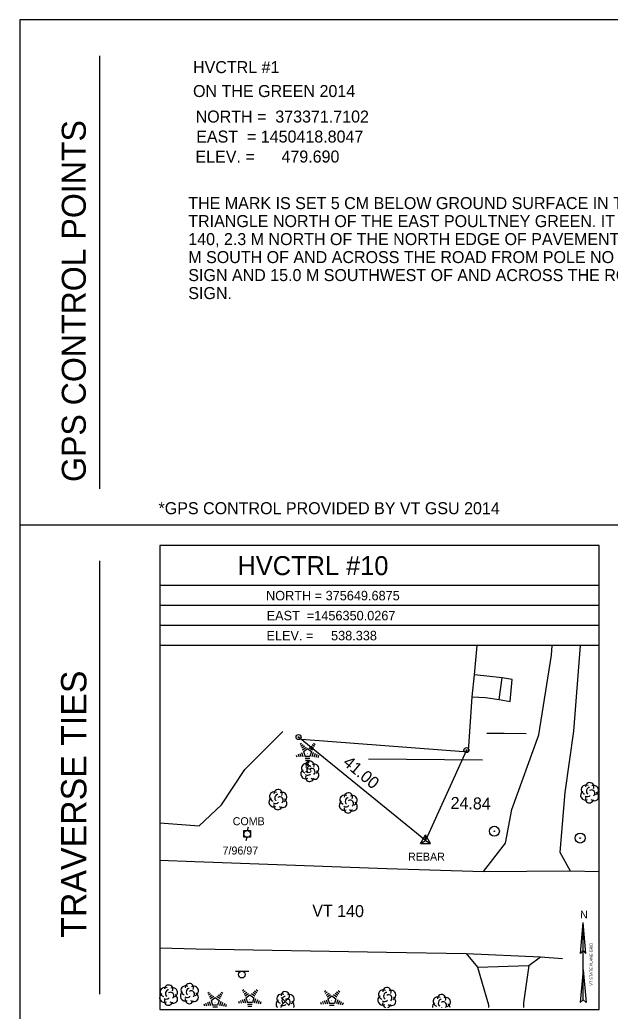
# Model space of a CAD drawing. Extents: x 1454446 to 1455086, y 375501 to 375921.
# Drawn here: x 1454446.4 to 1454594.1, y 375672.7 to 375920.6 of the extents above; entities that cross this region are included whole.
import ezdxf

# ---------------------------------------------------------------- set-up
doc = ezdxf.new("R2010")
doc.units = 0
for name, color, linetype in [('C_A', 7, 'Continuous'), ('CBP', 7, 'Continuous'), ('CPSM', 7, 'Continuous'), ('Default', 7, 'Continuous'), ('L_A', 7, 'Continuous'), ('L_TIC', 7, 'Continuous'), ('LAHR', 7, 'Continuous'), ('LAWA', 7, 'Continuous'), ('LBC', 7, 'Continuous'), ('LDEFAULT', 7, 'Continuous'), ('LTC', 7, 'Continuous'), ('LTD', 7, 'Continuous'), ('NBL1', 7, 'Continuous'), ('NBL2', 7, 'Continuous'), ('NNA_P', 7, 'Continuous'), ('PET', 7, 'Continuous'), ('RDG', 7, 'Continuous'), ('RDP', 7, 'Continuous'), ('RGP', 7, 'Continuous'), ('RSW', 7, 'Continuous'), ('SSGN', 7, 'Continuous'), ('U_A', 7, 'Continuous'), ('U_C', 7, 'Continuous'), ('UP', 7, 'Continuous')]:
    doc.layers.add(name, color=color, linetype=linetype)

msp = doc.modelspace()

# ---------------------------------------------------------------- linework, layer by layer
at = {"layer": 'CBP'}
for centre, radius in [((1454516.11, 375741.22), 0.625), ((1454516.11, 375741.22), 0.0833), ((1454558.12, 375737.95), 0.625), ((1454558.12, 375737.95), 0.0833)]:
    msp.add_circle(centre, radius, dxfattribs=at)
at = {"layer": 'CPSM'}
for p, q in [((1454546.66, 375714.58), (1454547.91, 375716.75)), ((1454549.16, 375714.58), (1454547.91, 375716.75)), ((1454547.91, 375715.31), (1454547.91, 375716.75)), ((1454546.66, 375714.58), (1454547.91, 375715.31)), ((1454546.66, 375714.58), (1454549.16, 375714.58)), ((1454547.91, 375715.31), (1454547.91, 375715.31)), ((1454547.91, 375715.31), (1454549.16, 375714.58))]:
    msp.add_line(p, q, dxfattribs=at)
at = {"layer": 'Default'}
for p, q in [((1454547.91, 375715.31), (1454516.11, 375741.22)), ((1454558.12, 375737.95), (1454547.91, 375715.31))]:
    msp.add_line(p, q, dxfattribs=at)
at = {"layer": 'L_TIC'}
for points in [[(1454511.74, 375674.07), (1454513.74, 375676.07)], [(1454513.74, 375674.07), (1454511.74, 375676.07)]]:
    msp.add_lwpolyline(points, dxfattribs=at)
at = {"layer": 'LAHR'}
for points in [[(1454563.24, 375742.16), (1454567.54, 375742.19), (1454573.08, 375742.15)], [(1454533.64, 375735.77), (1454562.16, 375735.5)]]:
    msp.add_lwpolyline(points, dxfattribs=at)
at = {"layer": 'LAWA'}
msp.add_lwpolyline([(1454481.37, 375719.77), (1454491.29, 375719), (1454496.85, 375724.26), (1454502.72, 375733.1), (1454512.21, 375742.64)], dxfattribs=at)
at = {"layer": 'LBC'}
msp.add_lwpolyline([(1454515.8, 375740.76), (1454558.56, 375737.56), (1454558.69, 375738.88), (1454559.56, 375751.32), (1454560.16, 375756.81), (1454560.84, 375764.1)], dxfattribs=at)
at = {"layer": 'LDEFAULT'}
msp.add_lwpolyline([(1454559.56, 375751.32), (1454562.87, 375751.13), (1454566.34, 375750.63), (1454567.11, 375756.03), (1454560.16, 375756.81)], dxfattribs=at)
at = {"layer": 'LTC'}
for p, q in [((1454516.5, 375739.44), (1454516.86, 375739.7)), ((1454516.71, 375738.97), (1454517.24, 375739.36)), ((1454516.92, 375738.51), (1454517.62, 375739.02)), ((1454517.13, 375738.04), (1454518.01, 375738.68)), ((1454517.35, 375737.59), (1454518.37, 375738.32)), ((1454518.37, 375738.32), (1454519.36, 375737.6)), ((1454518.79, 375738.64), (1454519.6, 375738.05)), ((1454519.16, 375738.98), (1454519.84, 375738.49)), ((1454519.53, 375739.33), (1454520.08, 375738.93)), ((1454519.9, 375739.68), (1454520.32, 375739.38)), ((1454515.53, 375736.72), (1454515.69, 375736.25)), ((1454515.99, 375736.94), (1454516.2, 375736.28)), ((1454516.44, 375737.15), (1454516.72, 375736.32)), ((1454516.9, 375737.37), (1454517.23, 375736.35)), ((1454517.35, 375737.59), (1454517.74, 375736.39)), ((1454518.97, 375736.39), (1454517.74, 375736.39)), ((1454518.93, 375735.89), (1454517.79, 375735.89)), ((1454518.85, 375735.39), (1454517.86, 375735.39)), ((1454519.36, 375737.6), (1454518.97, 375736.39)), ((1454519.8, 375737.33), (1454519.46, 375736.29)), ((1454520.25, 375737.08), (1454519.96, 375736.19)), ((1454520.69, 375736.83), (1454520.45, 375736.1)), ((1454521.13, 375736.58), (1454520.95, 375736)), ((1454518.77, 375734.89), (1454517.93, 375734.89)), ((1454518.68, 375734.39), (1454518.01, 375734.39)), ((1454493.39, 375677.19), (1454493.74, 375677.45)), ((1454493.6, 375676.73), (1454494.12, 375677.11)), ((1454493.81, 375676.26), (1454494.51, 375676.77)), ((1454494.01, 375675.8), (1454494.89, 375676.43)), ((1454494.24, 375675.34), (1454495.25, 375676.08)), ((1454495.25, 375676.08), (1454496.25, 375675.35)), ((1454495.67, 375676.39), (1454496.48, 375675.8)), ((1454496.04, 375676.74), (1454496.72, 375676.24)), ((1454496.41, 375677.09), (1454496.96, 375676.69)), ((1454496.78, 375677.43), (1454497.2, 375677.13)), ((1454502.09, 375677.85), (1454502.45, 375678.11)), ((1454502.3, 375677.39), (1454502.83, 375677.77)), ((1454502.49, 375675.78), (1454502.82, 375674.76)), ((1454502.51, 375676.92), (1454503.21, 375677.43)), ((1454502.72, 375676.46), (1454503.6, 375677.1)), ((1454502.94, 375676), (1454503.96, 375676.74)), ((1454502.94, 375676), (1454503.33, 375674.81)), ((1454503.96, 375676.74), (1454504.95, 375676.01)), ((1454504.38, 375677.05), (1454505.19, 375676.46)), ((1454504.95, 375676.01), (1454504.56, 375674.81)), ((1454504.75, 375677.4), (1454505.43, 375676.9)), ((1454505.39, 375675.74), (1454505.05, 375674.7)), ((1454505.12, 375677.75), (1454505.67, 375677.35)), ((1454505.49, 375678.09), (1454505.91, 375677.79)), ((1454522.62, 375677.61), (1454522.97, 375677.87)), ((1454522.82, 375677.14), (1454523.35, 375677.53)), ((1454523.03, 375676.68), (1454523.74, 375677.19)), ((1454523.24, 375676.21), (1454524.12, 375676.85)), ((1454523.47, 375675.76), (1454524.48, 375676.49)), ((1454523.47, 375675.76), (1454523.86, 375674.56)), ((1454524.48, 375676.49), (1454525.48, 375675.77)), ((1454524.9, 375676.8), (1454525.71, 375676.22)), ((1454525.48, 375675.77), (1454525.09, 375674.56)), ((1454525.27, 375677.15), (1454525.95, 375676.66)), ((1454525.64, 375677.5), (1454526.19, 375677.1)), ((1454526.01, 375677.85), (1454526.43, 375677.54)), ((1454492.42, 375674.47), (1454492.57, 375674)), ((1454492.87, 375674.69), (1454493.09, 375674.04)), ((1454493.33, 375674.91), (1454493.6, 375674.07)), ((1454493.78, 375675.12), (1454494.12, 375674.1)), ((1454494.24, 375675.34), (1454494.63, 375674.15)), ((1454495.86, 375674.15), (1454494.63, 375674.15)), ((1454495.82, 375673.65), (1454494.67, 375673.65)), ((1454496.25, 375675.35), (1454495.86, 375674.15)), ((1454496.69, 375675.08), (1454496.35, 375674.04)), ((1454497.13, 375674.83), (1454496.84, 375673.94)), ((1454497.57, 375674.58), (1454497.34, 375673.85)), ((1454498.02, 375674.33), (1454497.83, 375673.75)), ((1454501.12, 375675.13), (1454501.28, 375674.67)), ((1454501.58, 375675.35), (1454501.79, 375674.7)), ((1454502.03, 375675.57), (1454502.31, 375674.73)), ((1454504.56, 375674.81), (1454503.33, 375674.81)), ((1454504.52, 375674.31), (1454503.38, 375674.31)), ((1454504.44, 375673.81), (1454503.45, 375673.81)), ((1454505.83, 375675.49), (1454505.55, 375674.61)), ((1454506.28, 375675.24), (1454506.04, 375674.51)), ((1454506.72, 375674.99), (1454506.54, 375674.42)), ((1454521.65, 375674.89), (1454521.8, 375674.42)), ((1454522.1, 375675.1), (1454522.31, 375674.45)), ((1454522.56, 375675.32), (1454522.83, 375674.49)), ((1454523.01, 375675.54), (1454523.34, 375674.52)), ((1454525.09, 375674.56), (1454523.86, 375674.56)), ((1454525.05, 375674.06), (1454523.9, 375674.06)), ((1454525.91, 375675.5), (1454525.58, 375674.46)), ((1454526.36, 375675.24), (1454526.07, 375674.36)), ((1454526.8, 375674.99), (1454526.57, 375674.27)), ((1454527.25, 375674.74), (1454527.06, 375674.17))]:
    msp.add_line(p, q, dxfattribs=at)
at = {"layer": 'LTD'}
for p, q in [((1454518.92, 375732.69), (1454518.92, 375732.69)), ((1454518.92, 375732.69), (1454518.92, 375732.69)), ((1454510.94, 375725.63), (1454510.94, 375725.63)), ((1454510.94, 375725.63), (1454510.94, 375725.63)), ((1454588.93, 375727.34), (1454588.93, 375727.34)), ((1454588.93, 375727.34), (1454588.93, 375727.34)), ((1454528.55, 375724.81), (1454528.55, 375724.81)), ((1454528.55, 375724.81), (1454528.55, 375724.81)), ((1454483.58, 375676.73), (1454483.58, 375676.73)), ((1454483.58, 375676.73), (1454483.58, 375676.73)), ((1454488.78, 375677.12), (1454488.78, 375677.12)), ((1454488.78, 375677.12), (1454488.78, 375677.12)), ((1454538.18, 375676.11), (1454538.18, 375676.11)), ((1454538.18, 375676.11), (1454538.18, 375676.11)), ((1454512.74, 375675.07), (1454512.74, 375675.07)), ((1454512.74, 375675.07), (1454512.74, 375675.07))]:
    msp.add_line(p, q, dxfattribs=at)
for centre in [(1454518.97, 375734.13), (1454510.99, 375727.07), (1454588.98, 375728.77), (1454528.6, 375726.24), (1454483.63, 375678.16), (1454488.83, 375678.55), (1454538.23, 375677.54), (1454512.78, 375676.5), (1454551.9, 375675.77)]:
    msp.add_arc(centre, 1.05, 335.5272, 180.9563, dxfattribs=at)
for centre, major_axis, ratio, start_param, end_param in [((1454517.84, 375731.98), (0.58, -1.04), 0.959034, 3.141593, 6.283185), ((1454518.13, 375733.36), (1.21, -0.51), 0.895232, 1.570796, 4.712389), ((1454518.72, 375733.15), (-0.208, -0.792), 0.645439, 3.141593, 6.283185), ((1454519.42, 375732.53), (-0.5, 0.667), 0.989748, 3.141593, 6.283185), ((1454519.92, 375731.86), (-1.09, 0.79), 0.841452, 1.570796, 4.712389), ((1454519.97, 375733.28), (-1.14, -0.48), 0.949671, 1.570796, 4.712389), ((1454518.92, 375731.19), (0.26, 1.06), 0.942809, 1.570796, 4.712389), ((1454518.47, 375731.94), (-0.625, -0.083), 0.423636, 0, 3.141593), ((1454588.14, 375728.01), (1.21, -0.51), 0.895232, 1.570796, 4.712389), ((1454588.72, 375727.8), (-0.208, -0.792), 0.645439, 3.141593, 6.283185), ((1454589.43, 375727.17), (-0.5, 0.667), 0.989748, 3.141593, 6.283185), ((1454589.97, 375727.92), (-1.14, -0.48), 0.949671, 1.570796, 4.712389), ((1454509.86, 375724.92), (0.58, -1.04), 0.959034, 3.141593, 6.283185), ((1454510.15, 375726.3), (1.21, -0.51), 0.895232, 1.570796, 4.712389), ((1454510.73, 375726.09), (-0.208, -0.792), 0.645439, 3.141593, 6.283185), ((1454511.44, 375725.46), (-0.5, 0.667), 0.989748, 3.141593, 6.283185), ((1454511.94, 375724.8), (-1.09, 0.79), 0.841452, 1.570796, 4.712389), ((1454511.98, 375726.21), (-1.14, -0.48), 0.949671, 1.570796, 4.712389), ((1454527.76, 375725.48), (1.21, -0.51), 0.895232, 1.570796, 4.712389), ((1454528.34, 375725.27), (-0.208, -0.792), 0.645439, 3.141593, 6.283185), ((1454529.05, 375724.64), (-0.5, 0.667), 0.989748, 3.141593, 6.283185), ((1454529.59, 375725.39), (-1.14, -0.48), 0.949671, 1.570796, 4.712389), ((1454587.85, 375726.63), (0.58, -1.04), 0.959034, 3.141593, 6.283185), ((1454588.93, 375725.84), (0.26, 1.06), 0.942809, 1.570796, 4.712389), ((1454588.47, 375726.59), (-0.625, -0.083), 0.423636, 0, 3.141593), ((1454589.93, 375726.51), (-1.09, 0.79), 0.841452, 1.570796, 4.712389), ((1454510.94, 375724.13), (0.26, 1.06), 0.942809, 1.570796, 4.712389), ((1454510.48, 375724.88), (-0.625, -0.083), 0.423636, 0, 3.141593), ((1454527.47, 375724.1), (0.58, -1.04), 0.959034, 3.141593, 6.283185), ((1454528.55, 375723.31), (0.26, 1.06), 0.942809, 1.570796, 4.712389), ((1454528.09, 375724.06), (-0.625, -0.083), 0.423636, 0, 3.141593), ((1454529.55, 375723.98), (-1.09, 0.79), 0.841452, 1.570796, 4.712389), ((1454482.79, 375677.39), (1.21, -0.51), 0.895232, 1.570796, 4.712389), ((1454484.62, 375677.31), (-1.14, -0.48), 0.949671, 1.570796, 4.712389), ((1454487.99, 375677.79), (1.21, -0.51), 0.895232, 1.570796, 4.712389), ((1454488.58, 375677.58), (-0.208, -0.792), 0.645439, 3.141593, 6.283185), ((1454489.83, 375677.7), (-1.14, -0.48), 0.949671, 1.570796, 4.712389), ((1454482.5, 375676.02), (0.58, -1.04), 0.959034, 3.141593, 6.283185), ((1454483.12, 375675.98), (-0.625, -0.083), 0.423636, 0, 3.141593), ((1454483.37, 375677.19), (-0.208, -0.792), 0.645439, 3.141593, 6.283185), ((1454484.08, 375676.56), (-0.5, 0.667), 0.989748, 3.141593, 6.283185), ((1454484.58, 375675.89), (-1.09, 0.79), 0.841452, 1.570796, 4.712389), ((1454487.7, 375676.41), (0.58, -1.04), 0.959034, 3.141593, 6.283185), ((1454488.78, 375675.62), (0.26, 1.06), 0.942809, 1.570796, 4.712389), ((1454488.33, 375676.37), (-0.625, -0.083), 0.423636, 0, 3.141593), ((1454489.28, 375676.95), (-0.5, 0.667), 0.989748, 3.141593, 6.283185), ((1454489.78, 375676.29), (-1.09, 0.79), 0.841452, 1.570796, 4.712389), ((1454511.95, 375675.74), (1.21, -0.51), 0.895232, 1.570796, 4.712389), ((1454512.53, 375675.53), (-0.208, -0.792), 0.645439, 3.141593, 6.283185), ((1454513.24, 375674.9), (-0.5, 0.667), 0.989748, 3.141593, 6.283185), ((1454513.78, 375675.65), (-1.14, -0.48), 0.949671, 1.570796, 4.712389), ((1454537.1, 375675.4), (0.58, -1.04), 0.959034, 3.141593, 6.283185), ((1454537.39, 375676.78), (1.21, -0.51), 0.895232, 1.570796, 4.712389), ((1454537.97, 375676.57), (-0.208, -0.792), 0.645439, 3.141593, 6.283185), ((1454538.68, 375675.94), (-0.5, 0.667), 0.989748, 3.141593, 6.283185), ((1454539.18, 375675.28), (-1.09, 0.79), 0.841452, 1.570796, 4.712389), ((1454539.22, 375676.69), (-1.14, -0.48), 0.949671, 1.570796, 4.712389), ((1454551.06, 375675), (1.21, -0.51), 0.895232, 1.570796, 4.712389), ((1454552.89, 375674.92), (-1.14, -0.48), 0.949671, 1.570796, 4.712389), ((1454483.58, 375675.23), (0.26, 1.06), 0.942809, 1.570796, 4.712389), ((1454511.65, 375674.36), (0.58, -1.04), 0.959034, 3.141593, 4.952371), ((1454512.28, 375674.32), (-0.625, -0.083), 0.423636, 0, 3.141593), ((1454512.74, 375673.57), (0.26, 1.06), 0.942809, 1.570796, 1.801797), ((1454513.74, 375674.24), (-1.09, 0.79), 0.841452, 3.271651, 4.712389), ((1454538.18, 375674.61), (0.26, 1.06), 0.942809, 1.570796, 3.07315), ((1454537.72, 375675.36), (-0.625, -0.083), 0.423636, 0, 3.141593), ((1454538.18, 375674.61), (0.26, 1.06), 0.942809, 3.672659, 4.712389), ((1454550.77, 375673.63), (0.58, -1.04), 0.959034, 3.141593, 4.267083), ((1454551.64, 375674.79), (-0.208, -0.792), 0.645439, 3.141593, 6.283185), ((1454552.35, 375674.17), (-0.5, 0.667), 0.989748, 3.268895, 6.283185), ((1454551.39, 375673.58), (-0.625, -0.083), 0.423636, 2.782802, 3.141593), ((1454552.85, 375673.5), (-1.09, 0.79), 0.841452, 3.910504, 4.712389)]:
    msp.add_ellipse(centre, major_axis=major_axis, ratio=ratio, start_param=start_param, end_param=end_param, dxfattribs=at)
at = {"layer": 'NBL1'}
msp.add_lwpolyline([(1454446.38, 375500.6), (1455086.38, 375500.6), (1455086.38, 375920.6), (1454446.38, 375920.6)], close=True, dxfattribs=at)
at = {"layer": 'NBL2'}
for p, q in [((1454466.38, 375803.27), (1454466.38, 375911.6)), ((1454446.38, 375794.27), (1455086.38, 375794.27)), ((1454466.38, 375676.93), (1454466.38, 375785.27)), ((1454591.37, 375779.1), (1454481.37, 375779.1)), ((1454591.37, 375774.1), (1454481.37, 375774.1)), ((1454591.37, 375769.1), (1454481.37, 375769.1)), ((1454591.37, 375764.1), (1454481.37, 375764.1))]:
    msp.add_line(p, q, dxfattribs=at)
msp.add_lwpolyline([(1454481.37, 375673.1), (1454591.37, 375673.1), (1454591.37, 375789.1), (1454481.37, 375789.1)], close=True, dxfattribs=at)
at = {"layer": 'NNA_P'}
for p, q in [((1454586.64, 375687.06), (1454587.33, 375694.85)), ((1454587.33, 375675.47), (1454587.33, 375694.85)), ((1454588.02, 375687.06), (1454587.33, 375694.85)), ((1454586.64, 375687.06), (1454587.33, 375687.82)), ((1454588.03, 375687.06), (1454587.33, 375687.82)), ((1454587.34, 375683), (1454586.61, 375674.83)), ((1454587.33, 375683), (1454588.05, 375674.83)), ((1454587.33, 375675.47), (1454586.61, 375674.83)), ((1454587.33, 375675.47), (1454588.05, 375674.83))]:
    msp.add_line(p, q, dxfattribs=at)
at = {"layer": 'PET'}
for points in [[(1454481.37, 375710.41), (1454490.17, 375710.09), (1454538.2, 375708.32), (1454562.37, 375707.63), (1454584.1, 375707.8), (1454591.37, 375707.56)], [(1454481.37, 375688.53), (1454490.52, 375688.27), (1454538.1, 375687.4), (1454558.04, 375687.09), (1454576.68, 375686.22), (1454582.19, 375685.84)]]:
    msp.add_lwpolyline(points, dxfattribs=at)
at = {"layer": 'RDG'}
for points in [[(1454562.37, 375707.63), (1454567.94, 375714.69), (1454569.53, 375723.08), (1454576.27, 375741.78), (1454579.43, 375761.7), (1454579.6, 375764.1)], [(1454586.6, 375764.1), (1454584.88, 375742.71), (1454582.74, 375727.36), (1454581.52, 375712.44), (1454584.1, 375707.8)], [(1454560.93, 375683.63), (1454563.64, 375674.21), (1454563.68, 375673.57)], [(1454573.73, 375684.05), (1454572.44, 375674.75), (1454572.43, 375673.57)]]:
    msp.add_lwpolyline(points, dxfattribs=at)
at = {"layer": 'RDP'}
msp.add_lwpolyline([(1454558.04, 375687.09), (1454560.93, 375683.63), (1454573.73, 375684.05), (1454576.68, 375686.22)], dxfattribs=at)
at = {"layer": 'RGP'}
for p, q in [((1454565.12, 375717.66), (1454565.12, 375717.66)), ((1454586.59, 375715.97), (1454586.59, 375715.97))]:
    msp.add_line(p, q, dxfattribs=at)
for centre, radius in [((1454565.12, 375717.66), 1.25), ((1454565.12, 375717.66), 0.0833), ((1454586.59, 375715.97), 1.25), ((1454586.59, 375715.97), 0.0833)]:
    msp.add_circle(centre, radius, dxfattribs=at)
at = {"layer": 'RSW'}
msp.add_lwpolyline([(1454566.34, 375750.63), (1454569.05, 375750.14), (1454569.54, 375755.62), (1454567.11, 375756.03)], dxfattribs=at)
at = {"layer": 'SSGN'}
for p, q in [((1454500.31, 375682.64), (1454503.64, 375682.64)), ((1454501.95, 375681.81), (1454501.95, 375681.81))]:
    msp.add_line(p, q, dxfattribs=at)
msp.add_circle((1454501.95, 375681.81), 0.833, dxfattribs=at)
at = {"layer": 'UP'}
for p, q in [((1454503.5, 375718.65), (1454503.25, 375717.81)), ((1454502.42, 375716.15), (1454502.42, 375717.81)), ((1454502.42, 375717.81), (1454504.09, 375717.81)), ((1454504.09, 375716.15), (1454502.42, 375716.15)), ((1454503, 375715.31), (1454503.25, 375716.15)), ((1454503.25, 375716.98), (1454503.25, 375716.98)), ((1454504.09, 375717.81), (1454504.09, 375716.15))]:
    msp.add_line(p, q, dxfattribs=at)
msp.add_circle((1454503.25, 375716.98), 0.833, dxfattribs=at)

# ---------------------------------------------------------------- texts
at = {"layer": 'C_A'}
msp.add_text('REBAR', height=2, dxfattribs=at).set_placement((1454543.52, 375710.31))
at = {"layer": 'Default'}
for s, p in [('THE MARK IS SET 5 CM BELOW GROUND SURFACE IN THE TOP OF A FENO STYLE MONUMENT IN A SMALL GRASS ', (1454488.53, 375873.26)), ('TRIANGLE NORTH OF THE EAST POULTNEY GREEN. IT IS 6.4 M SOUTHWEST OF THE CENTERLINE OF VT ROUTE ', (1454488.53, 375868.76)), ('140, 2.3 M NORTH OF THE NORTH EDGE OF PAVEMENT OF THE ROAD PASSING SOUTH OF THE TRIANGLE, 18.0 ', (1454488.53, 375864.26)), ('M SOUTH OF AND ACROSS THE ROAD FROM POLE NO 7/78/78 WITH TRANSFORMER, 5.7 M EAST OF A STOP ', (1454488.53, 375859.76)), ('SIGN AND 15.0 M SOUTHWEST OF AND ACROSS THE ROAD FROM A WELCOME TO POULTNEY (ESTABLISHED 1761) ', (1454488.53, 375855.26)), ('SIGN.', (1454488.53, 375850.76)), ('*GPS CONTROL PROVIDED BY VT GSU 2014', (1454481.08, 375796.96))]:
    msp.add_text(s, height=3, dxfattribs=at).set_placement(p)
for s, rotation, p in [('41.00', 320.1146, (1454527.02, 375734.46)), ('24.84', 358.7799, (1454554.14, 375723.26)), ('VT 140', 359.3416, (1454519.53, 375696.33))]:
    msp.add_text(s, height=3, rotation=rotation, dxfattribs=at).set_placement(p)
at = {"layer": 'L_A'}
msp.add_text('S', height=2, dxfattribs=at).set_placement((1454517.69, 375732.23))
at = {"layer": 'LTC'}
for p in [(1454518.25, 375737.34), (1454495.13, 375675.09), (1454503.84, 375675.75), (1454524.36, 375675.5)]:
    msp.add_text('.', height=1.04, rotation=270, dxfattribs=at).set_placement(p)
at = {"layer": 'NBL2'}
for s, height, p in [('HVCTRL #1           ', 3, (1454489.72, 375907.27)), ('ON THE GREEN 2014   ', 3, (1454489.72, 375901.29)), ('NORTH =  373371.7102', 3, (1454490.36, 375894.91)), ('EAST  = 1450418.8047', 3, (1454490.51, 375889.91)), ('ELEV. =      479.690', 3, (1454490.33, 375884.91)), ('     HVCTRL #10    ', 4.75, (1454492.02, 375781.72)), ('NORTH = 375649.6875 ', 2.375, (1454507.99, 375775.41)), ('EAST  =1456350.0267 ', 2.375, (1454508.14, 375770.41)), ('ELEV. =     538.338 ', 2.375, (1454508.1, 375765.41))]:
    msp.add_text(s, height=height, dxfattribs=at).set_placement(p)
for s, height, p in [('GPS CONTROL POINTS', 6, (1454462.88, 375805.02)), ('TRAVERSE TIES', 6.3332, (1454463.04, 375691.03))]:
    msp.add_text(s, height=height, rotation=90, dxfattribs=at).set_placement(p)
at = {"layer": 'NNA_P'}
msp.add_text('N', height=1.97, dxfattribs=at).set_placement((1454586.57, 375695.86))
msp.add_text('VT STATE PLANE GRID', height=0.7, rotation=90.0204, dxfattribs=at).set_placement((1454589.68, 375679.04))
at = {"layer": 'U_A'}
msp.add_text('COMB', height=2, dxfattribs=at).set_placement((1454499.64, 375719.17))
at = {"layer": 'U_C'}
msp.add_text('7/96/97', height=2, dxfattribs=at).set_placement((1454497.1, 375711.84))

doc.saveas('drawing.dxf')
